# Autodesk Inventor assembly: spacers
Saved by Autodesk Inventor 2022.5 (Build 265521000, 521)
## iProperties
Created: 2024-12
Part Number: spacers
Document SubType Name: Assembly
Designer: AdminForWorker
Title: spacers
Author: AdminForWorker
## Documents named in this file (2)
- c:\worker\convert-fusion-r05-cosv3\tmp\job-1\35\temp\files\545dca92-a972-481a-9197-dd1a1176500e\spacers_1.iam
- c:\worker\convert-fusion-r05-cosv3\tmp\job-1\35\temp\files\545dca92-a972-481a-9197-dd1a1176500e\Component5_1.ipt
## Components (1 placed, 1 different names)
1. Component5:1
